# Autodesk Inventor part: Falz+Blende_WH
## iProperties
Created: 2008-06
Part Number: Falz+Blende_WH
Document SubType Name: Blech
Designer: Dirk
Density: 1 g/cm^3
Author: Dirk
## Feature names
1. Runde Anordnung3 [Circular Pattern]
2. Grobblech1
3. Grobblech2
4. Biegung1
5. Grobblech3
6. Biegung2
7. Grobblech4
8. Biegung3
9. Grobblech5
10. Biegung4
11. Grobblech6
12. Biegung5
13. Grobblech7
14. Biegung6
15. Ecke6
16. Ecke11
17. Ecke12
18. Ecke13
